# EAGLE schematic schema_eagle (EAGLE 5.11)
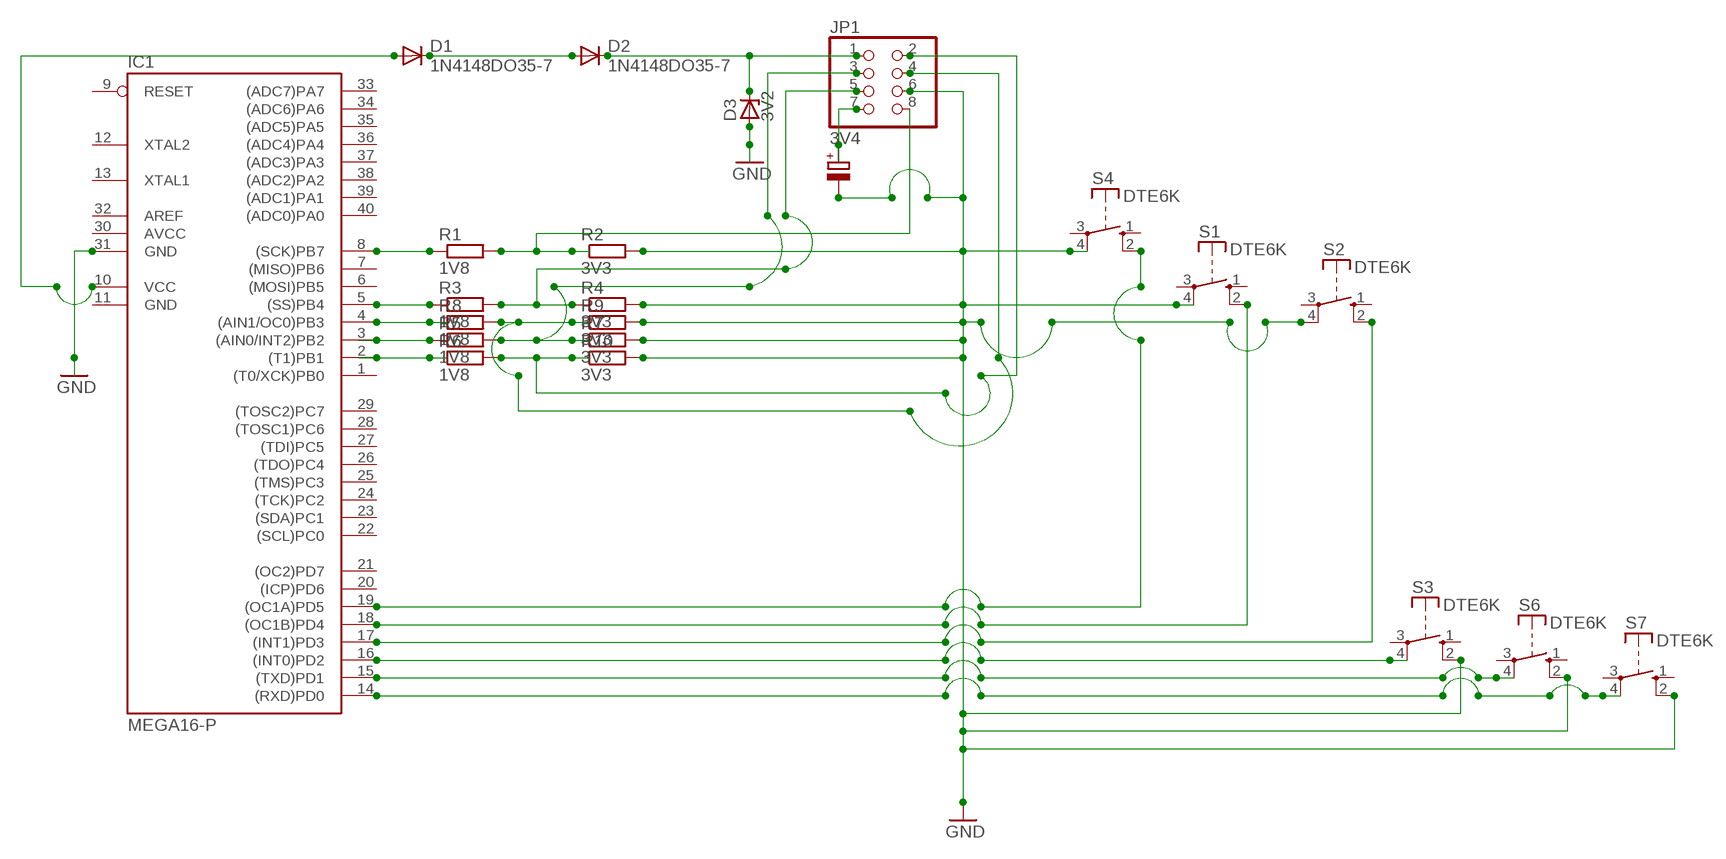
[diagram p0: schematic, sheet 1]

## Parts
D1  1N4148DO35-7  [DO35-7]
D2  1N4148DO35-7  [DO35-7]
D3  3V2  ZENER-DIODEC1702-15  [C1702-15]
IC1  MEGA16-P  [DIL40]
JP1  3V4  PINHD-2X4  [2X04]
R1  1V8  R-EU_0204/7  [0204/7]
R2  3V3  R-EU_0204/7  [0204/7]
R3  1V8  R-EU_0204/7  [0204/7]
R4  3V3  R-EU_0204/7  [0204/7]
R5  1V8  R-EU_0204/7  [0204/7]
R6  1V8  R-EU_0204/7  [0204/7]
R7  3V3  R-EU_0204/7  [0204/7]
R8  1V8  R-EU_0204/7  [0204/7]
R9  3V3  R-EU_0204/7  [0204/7]
R10  3V3  R-EU_0204/7  [0204/7]
S1  DTE6K  [DTE6K]
S2  DTE6K  [DTE6K]
S3  DTE6K  [DTE6K]
S4  DTE6K  [DTE6K]
S6  DTE6K  [DTE6K]
S7  DTE6K  [DTE6K]

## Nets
GND: D3.A IC1.31(GND) JP1.6 R2.2 R4.2 R7.2 R9.2 R10.2 S1.4(P) S2.4(P) S3.2(S) S4.4(P) S6.2(S) S7.2(S)
N$2: D1.A IC1.10(VCC)
N$3: D2.C D3.C JP1.1
N$4: IC1.8((SCK)PB7) R1.1
N$5: JP1.8 R1.2 R2.1
N$7: IC1.5((SS)PB4) R3.1
N$10: IC1.4((AIN1/OC0)PB3) R8.1
N$11: JP1.4 R8.2 R9.1
N$13: IC1.3((AIN0/INT2)PB2) R5.1
N$14: JP1.3 R5.2 R7.1
N$17: IC1.2((T1)PB1) R6.1
N$18: JP1.2 R6.2 R10.1
N$20: JP1.7
N$22: D1.C D2.A
N$23: IC1.19((OC1A)PD5) S4.2(S)
N$24: IC1.18((OC1B)PD4) S1.2(S)
N$26: IC1.16((INT0)PD2)
N$27: JP1.5 R3.2 R4.1
N$28: IC1.14((RXD)PD0) IC1.15((TXD)PD1) IC1.17((INT1)PD3) S2.2(S) S3.4(P) S6.4(P) S7.4(P)
Unconnected: IC1.1((T0/XCK)PB0) IC1.6((MOSI)PB5) IC1.7((MISO)PB6) IC1.9(RESET) IC1.12(XTAL2) IC1.13(XTAL1) IC1.20((ICP)PD6) IC1.21((OC2)PD7) IC1.22((SCL)PC0) IC1.23((SDA)PC1) IC1.24((TCK)PC2) IC1.25((TMS)PC3) IC1.26((TDO)PC4) IC1.27((TDI)PC5) IC1.28((TOSC1)PC6) IC1.29((TOSC2)PC7) IC1.32(AREF) IC1.33((ADC7)PA7) IC1.34((ADC6)PA6) IC1.35((ADC5)PA5) IC1.36((ADC4)PA4) IC1.37((ADC3)PA3) IC1.38((ADC2)PA2) IC1.39((ADC1)PA1) IC1.40((ADC0)PA0) S1.1(S) S1.3(P) S2.1(S) S2.3(P) S3.1(S) S3.3(P) S4.1(S) S4.3(P) S6.1(S) S6.3(P) S7.1(S) S7.3(P)

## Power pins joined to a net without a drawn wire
AVCC: IC1.30(AVCC)
GND: IC1.11(GND)

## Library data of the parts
D1 D2 = diode:1N4148: DIODE
D3 = diode:ZENER-DIODE: Z-Diode
IC1 = atmel:MEGA16-P: MICROCONTROLLER 16 Kbytes FLASH 1 kbytes SRAM 512 bytes EEPROM USART 8-channel 10 bit ADC Source: avr.lbr; MPN: ATMEGA16-16PU; OC_FARNELL: 9171142; OC_NEWARK: 01M6885
JP1 = pinhead:PINHD-2X4: PIN HEADER
R1-R10 = resistor:R-EU_: RESISTOR, European symbol
S1-S4 S6 S7 = switch-misc:DT: ITT SWITCH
